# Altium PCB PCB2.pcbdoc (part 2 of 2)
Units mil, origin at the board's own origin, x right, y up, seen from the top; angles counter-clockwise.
Board outline 7114.17 x 3886.41 mil, 4 copper layers (Top Layer, Inner1, Inner2, Bottom Layer); 197 components, 125 nets, 754 pads, 711 vias.
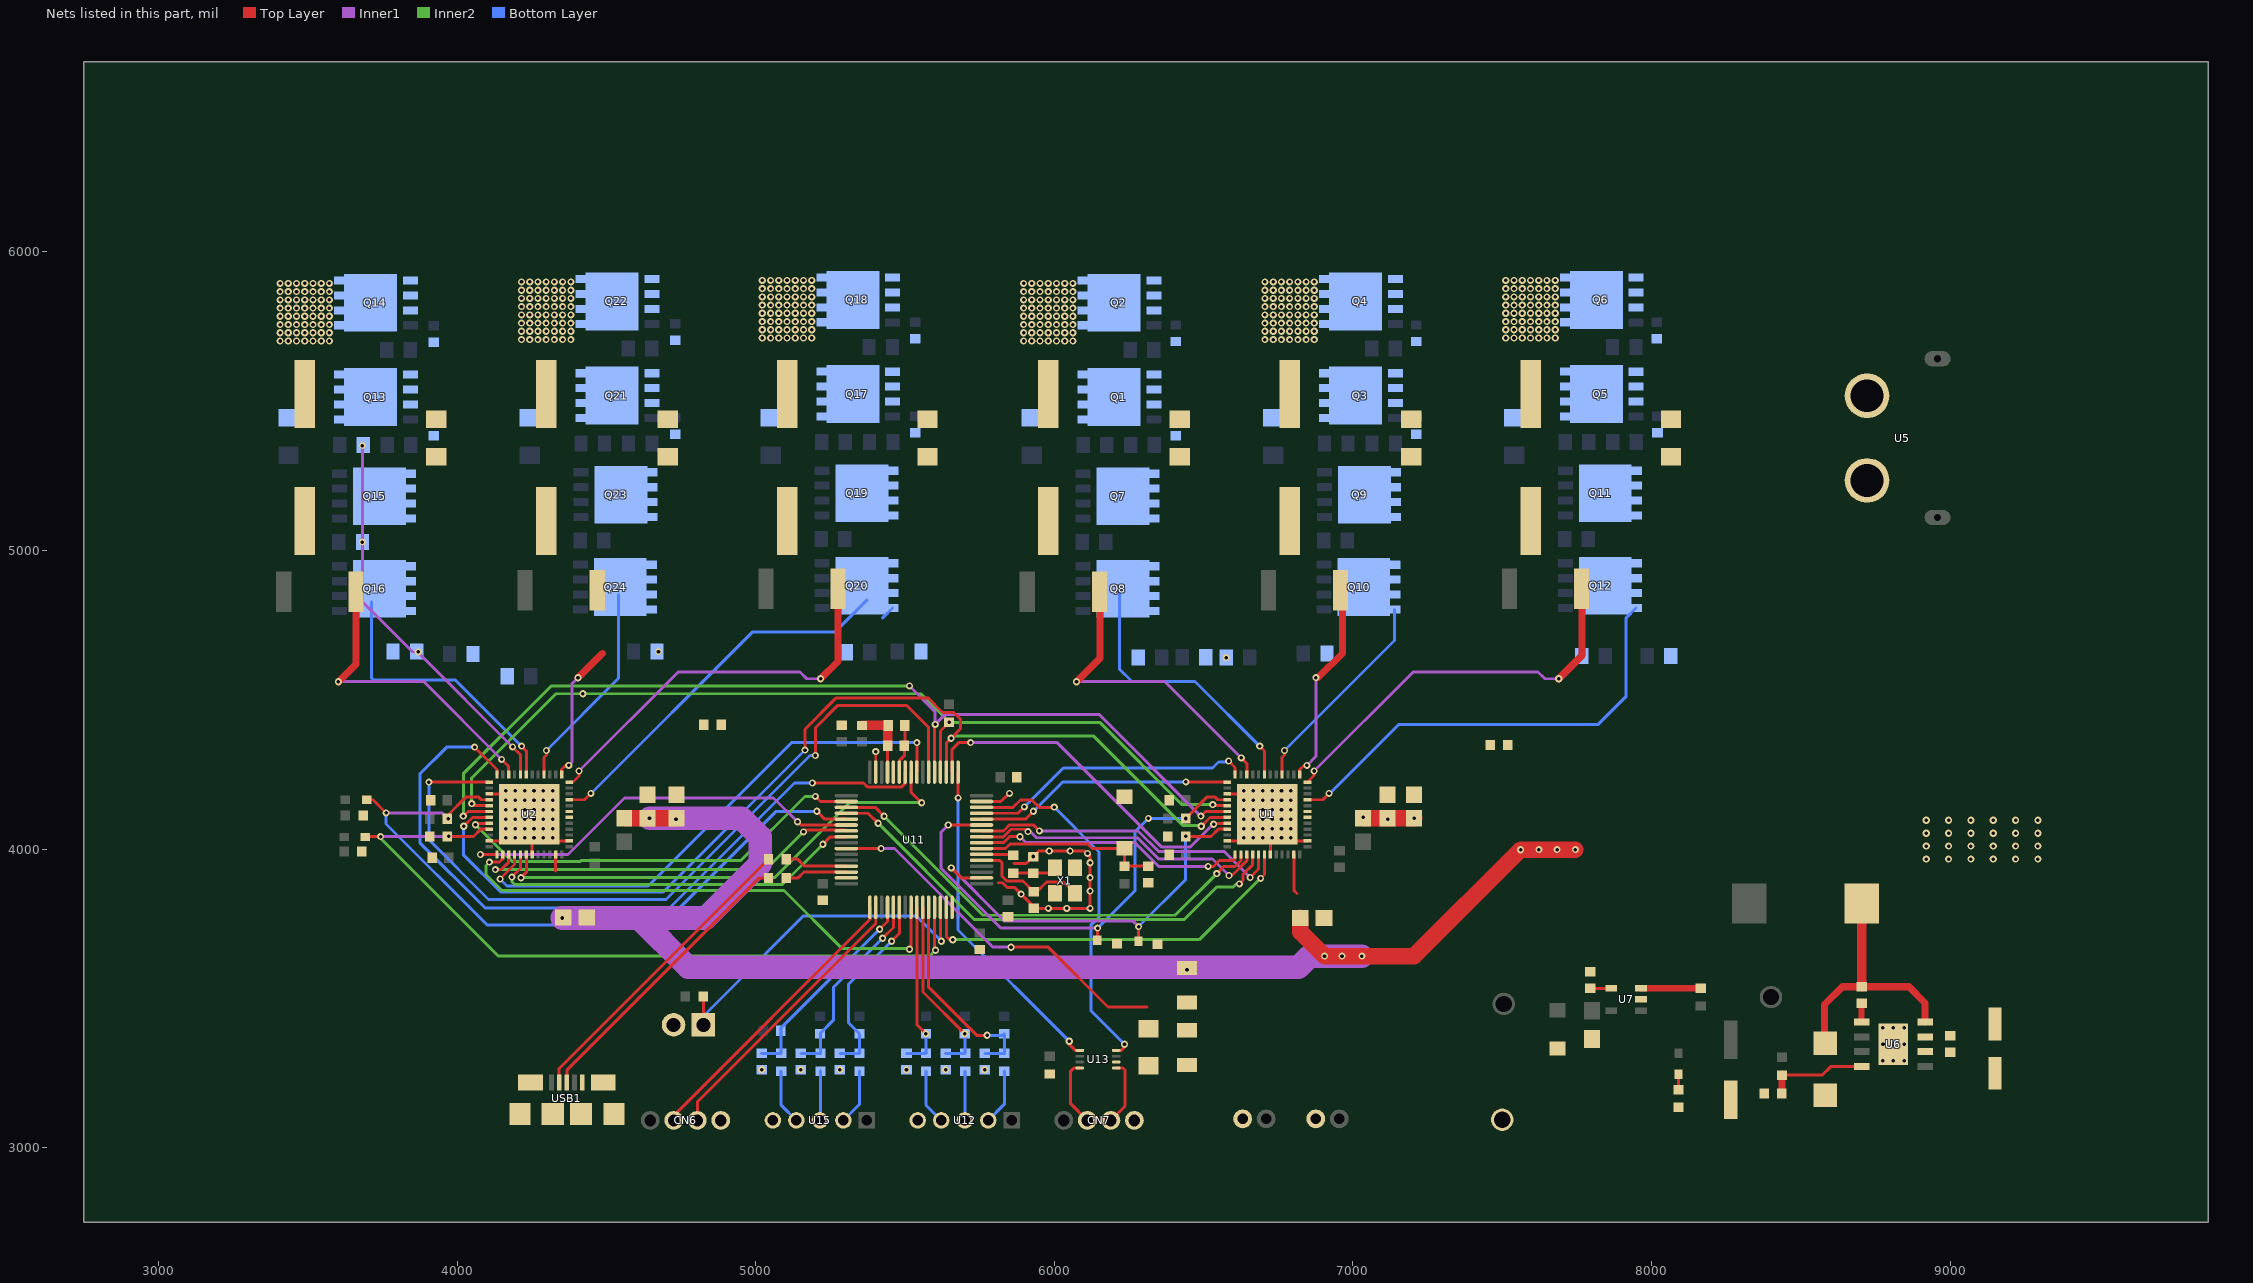
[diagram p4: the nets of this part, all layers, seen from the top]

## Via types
v1: diameter 24.02, hole 12.01, Top Layer to Bottom Layer, 707 vias
v2: diameter 236.22, hole 165.35, Top Layer to Bottom Layer, 4 vias

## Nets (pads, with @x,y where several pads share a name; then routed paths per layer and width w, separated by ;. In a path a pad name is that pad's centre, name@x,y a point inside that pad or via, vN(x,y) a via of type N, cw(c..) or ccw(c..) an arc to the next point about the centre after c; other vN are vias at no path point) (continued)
$1I3034\GL_C: R25.2 R43.2 R44.1 U2.20 | length 1331.4
  Top Layer w10: v1(4185.95,4342.16) 4212.2,4315.91 U2.20@4212.21,4250.15
  Inner1 w10: v1(3682.92,5351.41) v1(3682.92,5028.07) 3682.92,4828.7 3851.29,4660.34 v1(3869.92,4660.34) 3869.92,4658.19 v1(4185.95,4342.16)
$1N551: R75.1 R78.2 U6.4 | length 340.3
  Top Layer w10: R75.1@8436.66,3242.76 8571.35,3242.76 8600,3271.41 U6.4@8703.7,3271.41
  Top Layer w23.62: R78.2@8436.66,3181.41 R75.1@8436.66,3242.76
$1N561: C63.2 U6.1 | length 62.4
  Top Layer w19.68: U6.1@8703.7,3421.41 C63.2@8703.7,3483.85
$1N2428: C68.2 U7.4 | length 69.9
  Top Layer w10: C68.2@7795.03,3533.82 U7.4@7864.94,3533.82
$1N2597: R73.1 U7.3 | length 199.9
  Top Layer w21.65: U7.3@7965.06,3533.82 R73.1@8165,3533.82
$1N72792: C77.1 U11.5 X1.1 | length 412.8
  Top Layer w10: U11.5@5756.37,3962.51 5816.79,3962.51 5825.53,3953.77 5825.53,3907.92 5840.71,3892.74 5895.3,3892.74 C77.1@5930.76,3857.29 5941.45,3857.29 5974.12,3889.96 6030.68,3889.96 X1.1@6069.22,3851.42
$1N72945: R93.2 U11.6 | length 108.9
  Top Layer w10: U11.6@5756.37,3982.2 5861.79,3982.2 5862.27,3981.72 R93.2@5862.27,3978.92
$1N72949: C78.1 R93.1 X1.3 | length 147.7
  Top Layer w10: R93.1@5862.27,3919.6 C78.1@5928.95,3919.6 5983.86,3919.6 X1.3@6002.29,3938.04
$1N77944: R95.1 U11.46 | length 209.5
  Top Layer w10: R95.1@5102.19,3903.71 5142.3,3903.71 5161.73,3923.14 U11.46@5303.63,3923.14
$1N77945: R96.1 U11.45 | length 211
  Top Layer w10: R96.1@5102.19,3966.01 5140.4,3966.01 5163.58,3942.83 U11.45@5303.63,3942.83
$1N87601: LED5.1 R74.2 | length 51.6
  Top Layer w10: R74.2@8090,3194.38 LED5.1@8090,3245.98
$1N97516: R103.2 U12.4 | length 186.4
  Bottom Layer w10: R103.2@5570.53,3256.75 5570.53,3142.14 U12.4@5621.26,3091.41
$1N97530: R104.2 U12.3 | length 166
  Bottom Layer w10: U12.3@5700,3091.41 5701.58,3092.99 R104.2@5701.58,3256.75
$1N97534: R105.2 U12.2 | length 187.7
  Bottom Layer w10: U12.2@5778.74,3091.41 5832.63,3145.3 R105.2@5832.63,3256.75
$1N98528: R109.2 U15.4 | length 186.4
  Bottom Layer w10: R109.2@5085.53,3256.75 5085.53,3142.14 U15.4@5136.26,3091.41
$1N98530: R110.2 U15.3 | length 166
  Bottom Layer w10: U15.3@5215,3091.41 5216.58,3092.99 R110.2@5216.58,3256.75
$1N98532: R111.2 U15.2 | length 187.7
  Bottom Layer w10: U15.2@5293.74,3091.41 5347.63,3145.3 R111.2@5347.63,3256.75
AGND: C12.1 C13.1 C14.1 C15.1 C64.2 C65.2 C66.1 C67.2 C68.1 C69.1 C70.1 C71.1 C72.1 C73.1 C74.1 C75.1 C76.1 C77.2 C78.2 C80.1 C81.1 C82.1 C83.1 C84.1 C85.1 C86.1 CN3.1 CN4.2 CN5.2 CN6.1 CN7.1 D2.2 D3.2 H1.2 R19.1 R20.1 R21.1 R22.1 R24.1 R25.1 R26.1 R27.1 R28.1 R29.1 R30.1 R32.1 R33.1 R34.1 R35.1 R36.1 R37.1 R50.1 R74.1 R76.1 R77.1 R78.1 R87.1 R97.1 SW1.2 U1.2 U1.27 U1.35 U1.43 U1.49 U2.2 U2.27 U2.35 U2.43 U2.49 U6.6 U6.9 U7.2 U11.15 U11.27 U11.31 U11.47 U11.63 U12.5 U13.2 U15.5 USB1.5 USB1.6 X1.2 X1.4 | length 1610.1
  Top Layer w10: U2.35@4107.59,4027.42 U2.49@4153.15,4027.42 ; U2.27@4107.59,4184.9 4153.15,4184.9 v1(4162.99,4194.74) ; U2.49@4153.15,4022.5 U2.49@4162.99,4032.34 ; U2.43@4251.58,3981.85 4251.57,4031.35 v1(4257.48,4037.26) ; v1(4320.47,4037.26) 4330.31,4027.42 U2.2@4375.89,4027.42 ; U11.31@5402.05,4257.78 v1(5402.05,4326.41) ; U11.27@5480.79,4257.78 5480.79,4295.45 5497.56,4312.22 C75.1@5497.56,4346.41 5499.25,4348.1 C74.1@5499.25,4413.97 ; U11.15@5756.37,4159.36 5820.43,4159.36 5835.48,4174.4 5837.99,4174.4 v1(5850,4186.41) ; 5813.68,3887.25 5826.38,3887.25 5842.93,3870.7 5867.27,3870.7 v1(5888.9,3849.07) 5930.76,3807.21 C77.2@5930.76,3802.17 5931.51,3801.41 v1(5980.14,3801.41) v1(6041.48,3801.41) v1(6120,3801.41) v1(6120,3859.48) v1(6120,3904.39) v1(6120,3954.35) 6120,3976.41 6102.93,3993.48 v1(6052.86,3993.48) v1(5983.3,3993.48) 5947.71,3993.48 C78.2@5928.95,3974.72 ; 5865,3951.41 5905.91,3951.41 v1(5929.65,3975.15) ; U1.35@6579.37,4027.42 6624.94,4027.42 v1(6634.78,4037.26) ; U1.27@6579.37,4184.9 6624.94,4184.9 v1(6634.78,4194.74) ; U1.43@6723.36,3981.85 6723.36,4031.35 v1(6729.27,4037.26) ; v1(6792.26,4037.26) 6802.1,4027.42 U1.2@6847.67,4027.42
  other v1: 5020,3260.95 5151.05,3260.95 5282.1,3260.95 5505,3260.95 5636.05,3260.95 5767.1,3260.95 8775,3291.41 8810,3291.41 8845.83,3291.41 8775.1,3346.42 8810,3346.41 8845.83,3346.41 8775,3401.41 8810,3401.41 8845.83,3401.41 6111.06,3985.35 4162.99,4037.26 4194.49,4037.26 4225.98,4037.26 4288.97,4037.26 6666.27,4037.26 6697.77,4037.26 6760.76,4037.26 4162.99,4068.75 4194.49,4068.75 4225.98,4068.75 4257.48,4068.75 4288.97,4068.75 4320.47,4068.75 6634.78,4068.75 6666.27,4068.75 6697.77,4068.75 6729.27,4068.75 6760.76,4068.75 6792.26,4068.75 4162.99,4100.25 4194.49,4100.25 4225.98,4100.25 4257.48,4100.25 4288.97,4100.25 4320.47,4100.25 6634.78,4100.25 6666.27,4100.25 6697.77,4100.25 6729.27,4100.25 6760.76,4100.25 6792.26,4100.25 4162.99,4131.74 4194.49,4131.74 4225.98,4131.74 4257.48,4131.74 4288.97,4131.74 4320.47,4131.74 6634.78,4131.74 6666.27,4131.74 6697.77,4131.74 6729.27,4131.74 6760.76,4131.74 6792.26,4131.74 4162.99,4163.24 4194.49,4163.24 4225.98,4163.24 4257.48,4163.24 4288.97,4163.24 4320.47,4163.24 6634.78,4163.24 6666.27,4163.24 6697.77,4163.24 6729.27,4163.24 6760.76,4163.24 6792.26,4163.24 4194.49,4194.74 4225.98,4194.74 4257.48,4194.74 4288.97,4194.74 4320.47,4194.74 6666.27,4194.74 6697.77,4194.74 6729.27,4194.74 6760.76,4194.74 6792.26,4194.74 6575.63,4641.41 4674.43,4661.41
B1: CN7.3 U13.8 | length 222.7
  Top Layer w10: U13.8@6085.32,3266.88 6065.47,3266.88 6055,3256.41 6055,3147.04 CN7.3@6110.63,3091.41
B2: CN7.2 U13.1 | length 220.8
  Top Layer w10: CN7.2@6189.37,3091.41 6237.07,3139.11 6237.07,3259.81 6230,3266.88 U13.1@6207.36,3266.88
D+: R95.2 USB1.3 | length 983.3
  Top Layer w10: USB1.3@4367.66,3218.01 4367.66,3259.07 5012.3,3903.71 R95.2@5042.87,3903.71
D-: R96.2 USB1.2 | length 1038.3
  Top Layer w10: USB1.2@4342.07,3218.01 4342.07,3265.2 R96.2@5042.87,3966.01
M1_A: C30.1 C31.1 Q5.1 Q5.2 Q5.3 Q6.1 Q6.2 Q6.3 Q11.5 Q11.6 Q11.7 Q11.8 Q12.5 Q12.6 Q12.7 Q12.8 U1.9 | length 1520.2
  Top Layer w10: U1.9@6847.67,4165.21 6898.8,4165.21 v1(6920,4186.41)
  Bottom Layer w10: v1(6920,4186.41) 6922.48,4186.41 7152.48,4416.41 7820,4416.41 7915,4511.41 7915,4774.28 Q12.8@7947.93,4807.21
M1_B: C26.1 C27.1 Q3.1 Q3.2 Q3.3 Q4.1 Q4.2 Q4.3 Q9.5 Q9.6 Q9.7 Q9.8 Q10.5 Q10.6 Q10.7 Q10.8 U1.16 | length 708.3
  Top Layer w10: U1.16@6762.73,4250.15 6762.73,4307.14 6770.86,4315.27 v1(6770.86,4330.27)
  Bottom Layer w10: v1(6770.86,4330.27) 7139.15,4698.56 Q10.8@7139.15,4802.54
M1_C: C28.1 C29.1 Q1.1 Q1.2 Q1.3 Q2.1 Q2.2 Q2.3 Q7.5 Q7.6 Q7.7 Q7.8 Q8.5 Q8.6 Q8.7 Q8.8 U1.19 | length 951.9
  Top Layer w10: v1(6687.75,4344.67) 6703.68,4328.74 U1.19@6703.68,4250.15
  Bottom Layer w10: Q8.8@6230.17,4872.21 6217.93,4859.97 6217.93,4603.48 6260,4561.41 6471,4561.41 v1(6687.75,4344.67)
M2_A: C43.1 C44.1 Q17.1 Q17.2 Q17.3 Q18.1 Q18.2 Q18.3 Q19.5 Q19.6 Q19.7 Q19.8 Q20.5 Q20.6 Q20.7 Q20.8 U2.9 | length 1321.4
  Top Layer w10: U2.9@4375.89,4165.21 4427.01,4165.21 v1(4448.21,4186.41)
  Bottom Layer w10: v1(4448.21,4186.41) 4988.21,4726.41 5265,4726.41 Q20.8@5373.39,4834.8 ; 5425.18,4774.28 Q20.8@5458.11,4807.21
M2_B: C39.1 C40.1 Q21.1 Q21.2 Q21.3 Q22.1 Q22.2 Q22.3 Q23.5 Q23.6 Q23.7 Q23.8 Q24.5 Q24.6 Q24.7 Q24.8 U2.16 | length 704.9
  Top Layer w10: U2.16@4290.95,4250.15 4290.94,4307.14 4299.07,4315.27 v1(4299.07,4330.27)
  Bottom Layer w10: v1(4299.07,4330.27) 4540,4571.2 Q24.8@4540,4851.85
M2_C: C41.1 C42.1 Q13.1 Q13.2 Q13.3 Q14.1 Q14.2 Q14.3 Q15.5 Q15.6 Q15.7 Q15.8 Q16.5 Q16.6 Q16.7 Q16.8 U2.19 | length 952.2
  Top Layer w10: v1(4215.96,4344.67) 4231.89,4328.74 U2.19@4231.9,4250.15
  Bottom Layer w10: Q16.8@3712.93,4826.75 3712.93,4573.48 3720,4566.41 3994.22,4566.41 v1(4215.96,4344.67)
MISO: R94.1 U1.29 U2.29 U11.20 | length 3131.5
  Top Layer w10: v1(4048.85,4152.21) 4055.54,4145.53 U2.29@4109.37,4145.53 ; U11.20@5618.58,4257.78 5618.58,4395.65 v1(5648.09,4425.15) ; v1(6530.86,4148.83) 6534.16,4145.53 U1.29@6579.37,4145.53
  Inner2 w10: v1(4048.85,4152.21) 4048.85,4237.65 4331.36,4520.17 v1(4421.24,4520.17) 5553.07,4520.17 5623.84,4449.4 5624.52,4449.4 5637.99,4435.93 5637.99,4435.25 v1(5648.09,4425.15) 5648.84,4424.4 6152.01,4424.4 6427.58,4148.83 v1(6530.86,4148.83)
MOSI: U1.30 U2.30 U11.21 | length 3318.1
  Top Layer w10: v1(4020.86,4110.27) 4036.42,4125.84 U2.30@4109.37,4125.84 ; U11.21@5598.9,4257.78 5598.9,4415.31 v1(5601.26,4417.67) ; v1(6490.86,4110.27) 6506.42,4125.84 U1.30@6579.37,4125.84
  Inner1 w10: v1(5515,4546.41) 5601.26,4460.15 v1(5601.26,4417.67) 5635,4451.41 6149.71,4451.41 v1(6490.86,4110.27)
  Inner2 w10: v1(4020.86,4110.27) 4020.86,4252.27 4315,4546.41 v1(5515,4546.41)
NRST: C80.2 R98.1 SW1.1 U11.7 | length 631.3
  Top Layer w10: U11.7@5756.37,4001.88 5836.81,4001.88 5851.4,4016.47 6112.45,4016.47 6127.05,4001.88 6234.19,4001.88 SW1.1@6235,4002.69 R98.1@6235,3942.82 6314.06,3942.82 C80.2@6315,3941.88
PA0: U1.25 U11.12 | length 874.9
  Top Layer w10: U11.12@5756.37,4100.31 5903.9,4100.31 v1(5930,4126.41) ; v1(6440.52,4224.89) 6441.14,4224.27 U1.25@6579.37,4224.27
  Bottom Layer w10: v1(5930,4126.41) 6028.48,4224.89 v1(6440.52,4224.89)
PA1: U1.24 U11.13 | length 953.5
  Top Layer w10: U11.13@5756.37,4119.99 5878.58,4119.99 v1(5900,4141.41) ; v1(6583.81,4294.88) 6605.25,4273.45 U1.24@6605.25,4250.15
  Bottom Layer w10: v1(5900,4141.41) 6030,4271.41 6530,4271.41 6550,4291.41 6580.34,4291.41 v1(6583.81,4294.88)
PA4: U1.32 U11.18 | length 1185.3
  Top Layer w10: U11.18@5657.95,4257.78 5657.95,4334.36 5680,4356.41 v1(5719.57,4356.41) ; v1(6533.29,4083.16) 6536.59,4086.47 U1.32@6579.37,4086.47
  Inner1 w10: v1(5719.57,4356.41) 6010,4356.41 6360,4006.41 6454.51,4006.41 6531.27,4083.16 v1(6533.29,4083.16)
PA8: C76.2 R85.1 R87.2 U11.42 | length 1226.1
  Top Layer w10: U11.42@5303.63,4001.88 v1(5420,4001.88) ; v1(5855,3671.41) 5980,3671.41 6180,3471.41 6310,3471.41
  Inner1 w10: v1(5420,4001.88) 5464.53,4001.88 5795,3671.41 v1(5855,3671.41)
PA13: CN6.2 U11.50 | length 961.2
  Top Layer w10: CN6.2@4804.37,3091.41 4804.37,3153.3 5402.05,3750.98 U11.50@5402.05,3805.04
PA14: CN6.3 U11.49 | length 985.7
  Top Layer w10: CN6.3@4725.63,3091.41 4725.63,3107.04 5382.36,3763.77 U11.49@5382.36,3805.04
PB0: U2.40 U11.24 | length 1805.2
  Top Layer w10: v1(4144.08,3899.85) 4192.52,3948.29 U2.40@4192.53,3981.85 ; U11.24@5539.84,4257.78 5540,4257.94 v1(5540,4356.41)
  Bottom Layer w10: v1(4144.08,3899.85) 4167.52,3876.41 4640,3876.41 5120,4356.41 v1(5540,4356.41)
PB1: U2.42 U11.25 | length 1647.4
  Top Layer w10: v1(4214.06,3904.24) 4231.89,3922.06 U2.42@4231.9,3981.85 ; U11.25@5520.16,4257.78 5520.16,4190.72 v1(5555.46,4155.42)
  Inner2 w10: v1(4214.06,3904.24) 5062.83,3904.24 5314.01,4155.42 v1(5555.46,4155.42)
PB2: U2.24 U11.26 | length 2511.6
  Top Layer w10: v1(4058.55,4341.41) 4133.47,4266.49 U2.24@4133.47,4250.15 ; v1(5190,4221.41) 5361.38,4221.41 5375.36,4207.43 5487.79,4207.43 5500.47,4220.11 U11.26@5500.47,4257.78
  Bottom Layer w10: v1(4058.55,4341.41) 3965,4341.41 3875,4251.41 3875,4021.41 4094.02,3802.39 4710.98,3802.39 5130,4221.41 v1(5190,4221.41)
PB3: U2.38 U11.56 | length 1775.3
  Top Layer w10: v1(4108.21,3956.41) 4142.16,3956.41 4153.15,3967.4 U2.38@4153.16,3981.85 ; v1(5515,3664.4) 5520.16,3669.56 U11.56@5520.16,3805.04
  Inner2 w10: v1(4108.21,3956.41) 4096.53,3944.72 4096.53,3914.89 4150,3861.41 5095,3861.41 5290,3666.41 5512.99,3666.41 v1(5515,3664.4)
PB4: C81.2 R92.1 R103.1 U11.57 | length 567.1
  Top Layer w10: U11.57@5539.84,3805.04 5539.84,3411.57 v1(5570,3381.41)
  Bottom Layer w10: C81.2@5505,3316.07 R103.1@5570.53,3316.07 5570.53,3381.2 R92.1@5570.26,3381.46
PB5: C82.2 R91.1 R104.1 U11.58 | length 613.4
  Top Layer w10: U11.58@5559.53,3805.04 5560,3804.57 5560,3521.41 v1(5700,3381.41)
  Bottom Layer w10: C82.2@5636.05,3316.07 R104.1@5701.58,3316.07 5701.58,3379.88 R91.1@5700,3381.46
PB6: C83.2 R90.1 R105.1 U11.59 | length 720.9
  Top Layer w10: U11.59@5579.21,3805.04 5579.21,3537.2 5740,3376.41 v1(5775,3376.41)
  Bottom Layer w10: C83.2@5767.1,3316.07 R105.1@5832.63,3316.07 R90.1@5832.63,3381.46 5827.58,3376.41 v1(5775,3376.41)
PB7: LED4.2 R50.2 U2.33 U11.60 | length 2609.5
  Top Layer w10: LED4.2@3692.88,4040.21 3694.26,4041.59 v1(3743.77,4041.59) ; R50.2@3969.84,4042.3 4054.94,4042.3 4079.42,4066.79 U2.33@4109.37,4066.79 ; U11.60@5598.9,3805.04 5598.9,3664.71 v1(5602.2,3661.41)
  Inner1 w10: v1(3743.77,4041.59) 3970.77,4041.59 v1(3971.48,4042.3)
  Inner2 w10: v1(3743.77,4041.59) 3743.77,4036.59 4138.96,3641.41 5582.2,3641.41 v1(5602.2,3661.41)
PB8: H1.1 R99.1 U11.61 | length 1181.3
  Top Layer w10: R99.1@4823.98,3506.41 4825,3505.39 H1.1@4825,3411.41 ; U11.61@5618.58,3805.04 5618.58,3694.72 v1(5621.89,3691.41)
  Bottom Layer w10: H1.1@4825,3441.41 5160,3776.41 5536.89,3776.41 v1(5621.89,3691.41)
PB9: U1.42 U11.62 | length 1325.1
  Top Layer w10: U11.62@5638.27,3805.04 5638.27,3707.55 5649.41,3696.41 v1(5660,3696.41) ; v1(6690.85,3901.89) 6703.68,3914.72 U1.42@6703.68,3981.85
  Inner2 w10: v1(5660,3696.41) 6485.37,3696.41 v1(6690.85,3901.89)
PB12: U2.32 U11.34 | length 1438.5
  Top Layer w10: v1(4061.53,4081.41) 4066.59,4086.47 U2.32@4107.59,4086.47 ; v1(5200,4176.41) 5217.05,4159.36 U11.34@5303.63,4159.36
  Inner2 w10: v1(4061.53,4081.41) 4184.52,3958.42 4412.74,3958.42 4415.73,3961.41 4950,3961.41 5165,4176.41 v1(5200,4176.41)
PB13: U1.38 U11.35 | length 1567.2
  Top Layer w10: U11.35@5303.63,4139.68 5400,4139.68 v1(5430,4109.68) ; v1(6543.79,3917.71) 6567.48,3941.41 6605,3941.41 6624.94,3961.35 U1.38@6624.94,3981.85
  Inner2 w10: v1(5430,4109.68) 5761.26,3778.42 6404.49,3778.42 v1(6543.79,3917.71)
PB14: U1.40 U11.36 | length 1630.6
  Top Layer w10: U11.36@5303.63,4119.99 5376.42,4119.99 v1(5410,4086.41) ; v1(6620,3883.42) 6632.26,3895.68 6632.26,3915.68 6664.31,3947.73 U1.40@6664.31,3981.85
  Inner2 w10: v1(5410,4086.41) 5732.99,3763.42 6434.4,3763.42 6544.4,3873.42 6599.52,3873.42 6609.52,3883.42 v1(6620,3883.42)
PB15: LED3.2 R49.1 U2.28 U11.37 | length 2367
  Top Layer w10: LED3.2@3696.9,4165.21 3717.98,4165.21 v1(3762.08,4121.11) ; R49.1@3969.84,4102.48 3969.84,4114.38 4030.67,4175.21 4071.2,4175.21 4081.2,4165.21 U2.28@4109.37,4165.21 ; v1(5205,4126.41) 5231.1,4100.31 U11.37@5303.63,4100.31
  Inner1 w10: v1(3762.08,4121.11) 3950.3,4121.11 v1(3970,4101.41)
  Bottom Layer w10: v1(3762.08,4121.11) 3762.08,4084.33 4100.2,3746.21 4688.4,3746.21 5068.6,4126.41 v1(5205,4126.41)
PC0: U1.37 U11.8 | length 923.8
  Top Layer w10: U11.8@5756.37,4021.57 5830.16,4021.57 5850,4041.41 v1(5885,4041.41) ; v1(6515,3941.85) 6532.92,3941.85 6552.48,3961.41 6600,3961.41 6605.25,3966.66 U1.37@6605.25,3981.85
  Inner1 w10: v1(5885,4041.41) 5905,4021.41 6270,4021.41 6349.56,3941.85 v1(6515,3941.85)
PC1: U1.39 U11.9 | length 1004.1
  Top Layer w10: U11.9@5756.37,4041.25 5830.02,4041.25 5855.18,4066.41 5903.84,4066.41 v1(5911.83,4058.42) ; v1(6585,3911.41) 6594.82,3911.41 6644.62,3961.21 U1.39@6644.62,3981.85
  Inner1 w10: v1(5911.83,4058.42) 5920.01,4058.42 5940.48,4037.95 6278.46,4037.95 6350,3966.41 6530,3966.41 v1(6585,3911.41)
PC2: U1.41 U11.10 | length 1069.6
  Top Layer w10: U11.10@5756.37,4060.94 5829.89,4060.94 5850.36,4081.41 5929.53,4081.41 v1(5950,4060.94) ; v1(6655.85,3904.93) 6683.99,3933.07 U1.41@6683.99,3981.85
  Inner1 w10: v1(5950,4060.94) 6280.47,4060.94 6349.02,3992.39 6568.39,3992.39 v1(6655.85,3904.93)
PC3: LED1.2 R16.1 U1.28 U11.11 | length 1652.5
  Top Layer w10: v1(5645,4080.62) U11.11@5756.37,4080.62 ; LED1.2@6143.6,3694.04 6145.09,3695.53 v1(6145.09,3735.43) ; v1(6439.84,4102.48) 6512.56,4175.21 6536.99,4175.21 6546.99,4165.21 U1.28@6579.37,4165.21
  Inner1 w10: v1(5645,4080.62) 5620,4055.62 5620,3936.49 5821.06,3735.43 v1(6145.09,3735.43)
  Bottom Layer w10: v1(6145.09,3735.43) 6270,3860.34 6270,4057.63 v1(6315,4102.63) 6439.69,4102.63 v1(6439.84,4102.48)
PC4: U2.25 U11.22 | length 2655.6
  Top Layer w10: v1(3905.52,4224.27) U2.25@4107.59,4224.27 ; v1(5200,4313.42) 5200,4406.41 5275,4481.41 5505,4481.41 5579.21,4407.2 U11.22@5579.21,4257.78
  Bottom Layer w10: v1(3905.52,4224.27) 3905.52,4030.89 4105,3831.41 4700,3831.41 5182.01,4313.42 v1(5200,4313.42)
PC6: U2.37 U11.38 | length 1396.8
  Top Layer w10: v1(4078.21,3981.85) U2.37@4133.47,3981.85 ; v1(5140,4091.41) 5150.79,4080.62 U11.38@5303.63,4080.62
  Inner1 w10: v1(4078.21,3981.85) 4371.13,3981.85 4560.7,4171.41 5060,4171.41 v1(5140,4091.41)
PC7: U2.39 U11.39 | length 1312
  Top Layer w10: v1(4128.21,3931.41) 4148.21,3931.41 4172.83,3956.03 U2.39@4172.84,3981.85 ; v1(5160,4057.63) 5166.1,4063.73 5300.84,4063.73 U11.39@5303.63,4060.94
  Inner2 w10: v1(4128.21,3931.41) 5033.78,3931.41 v1(5160,4057.63)
PC8: U2.41 U11.40 | length 1293.1
  Top Layer w10: v1(4183.47,3906.16) 4212.2,3934.89 U2.41@4212.21,3981.85 ; v1(5225,4016.41) 5249.84,4041.25 U11.40@5303.63,4041.25
  Inner2 w10: v1(4183.47,3906.16) 4183.47,3891.25 4193.47,3881.25 5089.83,3881.25 v1(5225,4016.41)
PC10: C84.2 R108.1 R109.1 U11.52 | length 702.1
  Top Layer w10: v1(5415,3731.41) 5441.42,3757.83 U11.52@5441.42,3805.04
  Bottom Layer w10: C84.2@5020,3316.07 R109.1@5085.53,3316.07 5085.53,3381.2 5085.26,3381.46 5085.26,3401.67 v1(5415,3731.41)
PC11: C85.2 R107.1 R110.1 U11.53 | length 657.1
  Top Layer w10: v1(5425,3701.41) 5461.1,3737.51 U11.53@5461.1,3805.04
  Bottom Layer w10: C85.2@5151.05,3316.07 R110.1@5216.58,3316.07 5216.58,3379.88 R107.1@5215,3381.46 5260,3426.46 5260,3536.41 v1(5425,3701.41)
PC12: C86.2 R106.1 R111.1 U11.54 | length 640.8
  Top Layer w10: v1(5455,3691.41) 5480.79,3717.2 U11.54@5480.79,3805.04
  Bottom Layer w10: C86.2@5282.1,3316.07 R111.1@5347.63,3316.07 R106.1@5347.63,3381.46 5310,3419.09 5310,3546.41 v1(5455,3691.41)
PC13: LED2.2 R24.2 U1.33 U11.2 | length 1390.1
  Top Layer w10: v1(5654.65,3937.15) 5688.33,3903.46 U11.2@5756.37,3903.46 ; LED2.2@6282.12,3691.88 v1(6282.12,3740.43) ; v1(6439.84,4042.3) 6524.94,4042.3 6549.42,4066.79 U1.33@6579.37,4066.79
  Inner1 w10: v1(5654.65,3937.15) 5833.38,3758.42 6264.12,3758.42 v1(6282.12,3740.43)
  Bottom Layer w10: v1(6282.12,3740.43) 6439.84,3898.15 v1(6439.84,4042.3)
PGND: C1.1 C2.2 C3.1 C4.2 C5.1 C6.2 C10.2 C11.2 C18.2 C21.2 C22.2 C24.2 C25.2 C33.1 C34.1 C35.2 C37.1 C38.2 R13.1 R14.1 R15.1 R17.1 R18.1 R23.1 R76.2 R77.2 U1.12 U1.13 U1.22 U2.12 U2.13 U2.22 U5.4 | length 5935.5
  Top Layer w10: v1(4149.07,4300.27) 4172.84,4276.5 U2.22@4172.84,4250.15 ; U2.13@4350.01,4250.15 4350,4266.2 4364.07,4280.27 v1(4374.07,4280.27) ; U2.12@4375.89,4224.27 4387.85,4224.27 4408.21,4244.62 v1(4408.21,4261.41) ; v1(6625.86,4305.27) 6644.62,4286.51 U1.22@6644.62,4250.15 ; U1.13@6821.79,4250.15 6821.79,4266.2 6835.86,4280.27 v1(6845.86,4280.27) ; U1.12@6847.67,4224.27 6870,4246.6 v1(6870,4261.41)
  Top Layer w23.62: v1(3602.56,4560.44) 3660.9,4618.78 R17.1@3660.9,4861.41 ; v1(4404.9,4573.57) 4486.27,4654.94 ; v1(5217.56,4570.44) 5275.9,4628.78 R18.1@5275.9,4871.41 ; v1(6074.35,4560.44) 6152.94,4639.03 6152.94,4859.19 R13.1@6150.72,4861.41 ; v1(6876.1,4574.07) 6883.63,4574.07 6965,4655.44 6965,4860.4 R14.1@6959.12,4866.28 ; v1(7689.35,4570.44) 7767.94,4649.03 7767.94,4869.19 R15.1@7765.72,4871.41
  Inner1 w10: v1(3602.56,4560.44) 3888.9,4560.44 v1(4149.07,4300.27) ; v1(4374.07,4280.27) 4385,4291.2 4385,4553.67 v1(4404.9,4573.57) ; v1(4408.21,4261.41) 4740.23,4593.43 5148.34,4593.43 5171.34,4570.44 v1(5217.56,4570.44) ; v1(6074.35,4560.44) 6370.68,4560.44 v1(6625.86,4305.27) ; v1(6845.86,4280.27) 6876.1,4310.51 v1(6876.1,4574.07) ; v1(6870,4261.41) 7202.02,4593.43 7620.13,4593.43 7643.12,4570.44 v1(7689.35,4570.44)
PH: C63.1 D2.1 L3.2 U6.8 | length 858.2
  Top Layer w23.62: D2.1@8580,3347.73 8580,3478.85 8579.68,3479.17 8639.48,3538.97 C63.1@8703.7,3538.97 8862.44,3538.97 8916.3,3485.12 U6.8@8916.3,3421.41
  Top Layer w31.5: C63.1@8703.7,3538.97 L3.2@8703.7,3818.21
SCK: U1.31 U2.31 U11.19 | length 3514
  Top Layer w10: v1(4022.1,4076.51) 4051.74,4106.16 U2.31@4109.37,4106.16 ; v1(5165,4331.41) 5165,4401.23 5270.18,4506.41 5577.13,4506.41 5625.97,4457.57 5663.49,4457.57 5685.84,4435.22 5685.84,4402.68 v1(5654.57,4371.41) 5638.27,4355.11 U11.19@5638.27,4257.78 ; v1(6492.1,4076.51) 6521.74,4106.16 U1.31@6579.37,4106.16
  Inner2 w10: v1(5654.57,4371.41) 5662.56,4379.4 6130.4,4379.4 6430.31,4079.49 6489.12,4079.49 v1(6492.1,4076.51)
  Bottom Layer w10: v1(4022.1,4076.51) 4022.1,3979.31 4145,3856.41 4690,3856.41 v1(5165,4331.41)
UART_RX: U11.17 U13.5 | length 1109.4
  Top Layer w10: v1(5677.64,4171.41) U11.17@5677.64,4257.78 ; v1(6050,3356.41) 6050,3346.41 6070.47,3325.94 U13.5@6085.32,3325.94
  Bottom Layer w10: v1(5677.64,4171.41) 5677.64,3728.77 v1(6050,3356.41)
UART_TX: U11.14 U13.4 | length 1221.1
  Top Layer w10: U11.14@5756.37,4139.68 5861.76,4139.68 5886.48,4164.4 5924.52,4164.4 5949.25,4139.68 5999.06,4139.68 v1(6000,4140.62) ; U13.4@6207.36,3325.94 6224.53,3325.94 6235,3336.41 v1(6235,3346.41)
  Bottom Layer w10: v1(6000,4140.62) 6150,3990.62 6150,3772.86 6122.09,3744.95 6122.09,3459.32 v1(6235,3346.41)
VDDA: C74.2 C75.2 L4.2 U11.28 U11.29 | length 245
  Top Layer w10: U11.29@5441.42,4257.78 5441.42,4345.39 C75.2@5442.44,4346.41
  Top Layer w31.73: L4.2@5356.35,4413.94 5444.09,4413.94 5442.44,4412.29 C75.2@5442.44,4346.41
VM: C1.2 C2.1 C3.2 C4.1 C5.2 C6.1 C7.2 C8.2 C9.2 C10.1 C11.1 C17.2 C18.1 C20.2 C21.1 C22.1 C23.2 C24.1 C25.1 C32.2 C33.2 C34.2 C35.1 C36.2 C37.2 C38.1 C66.2 C67.1 Q1.5 Q1.6 Q1.7 Q1.8 Q2.5 Q2.6 Q2.7 Q2.8 Q3.5 Q3.6 Q3.7 Q3.8 Q4.5 Q4.6 Q4.7 Q4.8 Q5.5 Q5.6 Q5.7 Q5.8 Q6.5 Q6.6 Q6.7 Q6.8 Q13.5 Q13.6 Q13.7 Q13.8 Q14.5 Q14.6 Q14.7 Q14.8 Q17.5 Q17.6 Q17.7 Q17.8 Q18.5 Q18.6 Q18.7 Q18.8 Q21.5 Q21.6 Q21.7 Q21.8 Q22.5 Q22.6 Q22.7 Q22.8 R85.2 U1.6 U1.7 U1.47 U2.6 U2.7 U2.47 U5.3 U6.7 | length 5409.5
  Top Layer w10: 4330,3926.41 4330,3981.54 U2.47@4330.32,3981.85 ; U1.47@6802.1,3981.85 6802.1,3861.77 6812.46,3851.41
  Top Layer w55.51: C17.2@4562.58,4103.59 v1(4644.47,4103.59) C38.1@4733.21,4103.59 ; C24.1@6824.34,3769.2 6824.34,3722.07 v1(6905,3641.41) v1(6963.36,3641.41) v1(7030.22,3641.41) 7205,3641.41 v1(7561.55,3997.96) 7561.78,3998.19 v1(7622.7,3998.19) v1(7683.85,3998.19) v1(7745,3998.19) ; C20.2@7034.37,4103.59 C21.1@7116.26,4103.59 v1(7205,4103.59)
  Inner1 w78.74: v1(4352.55,3769.2) 4608.98,3769.2 ; v1(4644.47,4103.59) 4952.14,4103.59 5015,4040.73 5015,3951.41 4832.79,3769.2 4608.98,3769.2 ; v1(7030.22,3641.41) v1(6963.36,3641.41) v1(6905,3641.41) 6855,3641.41 6817.64,3604.05 4774.14,3604.05 4608.98,3769.2
  other v1: 6444.27,3596.09 8920,3966.49 8994.8,3966.49 9069.61,3966.49 9144.41,3966.49 9219.21,3966.49 9294.02,3966.49 8920,4009.8 8994.8,4009.8 9069.61,4009.8 9144.41,4009.8 9219.21,4009.8 9294.02,4009.8 8920,4053.1 8994.8,4053.1 9069.61,4053.1 9144.41,4053.1 9219.21,4053.1 9294.02,4053.1 8920,4096.41 8994.8,4096.41 9069.61,4096.41 9144.41,4096.41 9219.21,4096.41 9294.02,4096.41 4733.21,4100.54 7116.26,4100.54 7034.37,4106.64 3407.18,5701.49 3434.74,5701.49 3462.3,5701.49 3489.86,5701.49 3517.42,5701.49 3544.98,5701.49 3572.54,5701.49 5897.01,5701.49 5924.57,5701.49 5952.13,5701.49 5979.69,5701.49 6007.24,5701.49 6034.8,5701.49 6062.36,5701.49 4215.59,5706.36 4243.14,5706.36 4270.7,5706.36 4298.26,5706.36 4325.82,5706.36 4353.38,5706.36 4380.94,5706.36 6705.41,5706.36 6732.97,5706.36 6760.53,5706.36 6788.09,5706.36 6815.65,5706.36 6843.2,5706.36 6870.76,5706.36 5022.18,5711.49 5049.74,5711.49 5077.3,5711.49 5104.86,5711.49 5132.42,5711.49 5159.98,5711.49 5187.54,5711.49 7512.01,5711.49 7539.57,5711.49 7567.13,5711.49 7594.69,5711.49 7622.24,5711.49 7649.8,5711.49 7677.36,5711.49 3407.18,5729.05 3434.74,5729.05 3462.3,5729.05 3489.86,5729.05 3517.42,5729.05 3544.98,5729.05 3572.54,5729.05 5897.01,5729.05 5924.57,5729.05 5952.13,5729.05 5979.69,5729.05 6007.24,5729.05 6034.8,5729.05 6062.36,5729.05 4215.59,5733.92 4243.14,5733.92 4270.7,5733.92 4298.26,5733.92 4325.82,5733.92 4353.38,5733.92 4380.94,5733.92 6705.41,5733.92 6732.97,5733.92 6760.53,5733.92 6788.09,5733.92 6815.65,5733.92 6843.2,5733.92 6870.76,5733.92 5022.18,5739.05 5049.74,5739.05 5077.3,5739.05 5104.86,5739.05 5132.42,5739.05 5159.98,5739.05 5187.54,5739.05 7512.01,5739.05 7539.57,5739.05 7567.13,5739.05 7594.69,5739.05 7622.24,5739.05 7649.8,5739.05 7677.36,5739.05 3407.18,5756.61 3434.74,5756.61 3462.3,5756.61 3489.86,5756.61 3517.42,5756.61 3544.98,5756.61 3572.54,5756.61 5897.01,5756.61 5924.57,5756.61 5952.13,5756.61 5979.69,5756.61 6007.24,5756.61 6034.8,5756.61 6062.36,5756.61 4215.59,5761.48 4243.14,5761.48 4270.7,5761.48 4298.26,5761.48 4325.82,5761.48 4353.38,5761.48 4380.94,5761.48 6705.41,5761.48 6732.97,5761.48 6760.53,5761.48 6788.09,5761.48 6815.65,5761.48 6843.2,5761.48 6870.76,5761.48 5022.18,5766.61 5049.74,5766.61 5077.3,5766.61 5104.86,5766.61 5132.42,5766.61 5159.98,5766.61 5187.54,5766.61 7512.01,5766.61 7539.57,5766.61 7567.13,5766.61 7594.69,5766.61 7622.24,5766.61 7649.8,5766.61 7677.36,5766.61 3407.18,5784.17 3434.74,5784.17 3462.3,5784.17 3489.86,5784.17 3517.42,5784.17 3544.98,5784.17 3572.54,5784.17 5897.01,5784.17 5924.57,5784.17 5952.13,5784.17 5979.69,5784.17 6007.24,5784.17 6034.8,5784.17 6062.36,5784.17 4215.59,5789.04 4243.14,5789.04 4270.7,5789.04 4298.26,5789.04 4325.82,5789.04 4353.38,5789.04 4380.94,5789.04 6705.41,5789.04 6732.97,5789.04 6760.53,5789.04 6788.09,5789.04 6815.65,5789.04 6843.2,5789.04 6870.76,5789.04 5022.18,5794.17 5049.74,5794.17 5077.3,5794.17 5104.86,5794.17 5132.42,5794.17 5159.98,5794.17 5187.54,5794.17 7512.01,5794.17 7539.57,5794.17 7567.13,5794.17 7594.69,5794.17 7622.24,5794.17 7649.8,5794.17 7677.36,5794.17 3407.18,5811.73 3434.74,5811.73 3462.3,5811.73 3489.86,5811.73 3517.42,5811.73 3544.98,5811.73 3572.54,5811.73 5897.01,5811.73 5924.57,5811.73 5952.13,5811.73 5979.69,5811.73 6007.24,5811.73 6034.8,5811.73 6062.36,5811.73 4215.59,5816.59 4243.14,5816.59 4270.7,5816.59 4298.26,5816.59 4325.82,5816.59 4353.38,5816.59 4380.94,5816.59 6705.41,5816.59 6732.97,5816.59 6760.53,5816.59 6788.09,5816.59 6815.65,5816.59 6843.2,5816.59 6870.76,5816.59 5022.18,5821.73 5049.74,5821.73 5077.3,5821.73 5104.86,5821.73 5132.42,5821.73 5159.98,5821.73 5187.54,5821.73 7512.01,5821.73 7539.57,5821.73 7567.13,5821.73 7594.69,5821.73 7622.24,5821.73 7649.8,5821.73 7677.36,5821.73 3407.18,5839.28 3434.74,5839.28 3462.3,5839.28 3489.86,5839.28 3517.42,5839.28 3544.98,5839.28 3572.54,5839.28 5897.01,5839.28 5924.57,5839.28 5952.13,5839.28 5979.69,5839.28 6007.24,5839.28 6034.8,5839.28 6062.36,5839.28 4215.59,5844.15 4243.14,5844.15 4270.7,5844.15 4298.26,5844.15 4325.82,5844.15 4353.38,5844.15 4380.94,5844.15 6705.41,5844.15 6732.97,5844.15 6760.53,5844.15 6788.09,5844.15 6815.65,5844.15 6843.2,5844.15 6870.76,5844.15 5022.18,5849.28 5049.74,5849.28 5077.3,5849.28 5104.86,5849.28 5132.42,5849.28 5159.98,5849.28 5187.54,5849.28 7512.01,5849.28 7539.57,5849.28 7567.13,5849.28 7594.69,5849.28 7622.24,5849.28 7649.8,5849.28 7677.36,5849.28 3407.18,5866.84 3434.74,5866.84 3462.3,5866.84 3489.86,5866.84 3517.42,5866.84 3544.98,5866.84 3572.54,5866.84 5897.01,5866.84 5924.57,5866.84 5952.13,5866.84 5979.69,5866.84 6007.24,5866.84 6034.8,5866.84 6062.36,5866.84 4215.59,5871.71 4243.14,5871.71 4270.7,5871.71 4298.26,5871.71 4325.82,5871.71 4353.38,5871.71 4380.94,5871.71 6705.41,5871.71 6732.97,5871.71 6760.53,5871.71 6788.09,5871.71 6815.65,5871.71 6843.2,5871.71 6870.76,5871.71 5022.18,5876.84 5049.74,5876.84 5077.3,5876.84 5104.86,5876.84 5132.42,5876.84 5159.98,5876.84 5187.54,5876.84 7512.01,5876.84 7539.57,5876.84 7567.13,5876.84 7594.69,5876.84 7622.24,5876.84 7649.8,5876.84 7677.36,5876.84 3407.18,5894.4 3434.74,5894.4 3462.3,5894.4 3489.86,5894.4 3517.42,5894.4 3544.98,5894.4 3572.54,5894.4 5897.01,5894.4 5924.57,5894.4 5952.13,5894.4 5979.69,5894.4 6007.24,5894.4 6034.8,5894.4 6062.36,5894.4 4215.59,5899.27 4243.14,5899.27 4270.7,5899.27 4298.26,5899.27 4325.82,5899.27 4353.38,5899.27 4380.94,5899.27 6705.41,5899.27 6732.97,5899.27 6760.53,5899.27 6788.09,5899.27 6815.65,5899.27 6843.2,5899.27 6870.76,5899.27 5022.18,5904.4 5049.74,5904.4 5077.3,5904.4 5104.86,5904.4 5132.42,5904.4 5159.98,5904.4 5187.54,5904.4 7512.01,5904.4 7539.57,5904.4 7567.13,5904.4 7594.69,5904.4 7622.24,5904.4 7649.8,5904.4 7677.36,5904.4
pads on no net: U1.1 U1.23 U1.34 U1.44 U1.45 U1.46 U1.48 U2.1 U2.23 U2.34 U2.44 U2.45 U2.46 U2.48 U5.1 U5.2 U6.2 U6.3 U6.5 U11.3 U11.4 U11.23 U11.30 U11.33 U11.41 U11.43 U11.44 U11.51 U11.55 USB1.1 USB1.4
copper on no net: | length 151.1
  Top Layer w10: 6821.79,3981.85 6821.79,3949.62 6871.78,3899.63 6871.78,3851.41
  other v2: 3157.48,3158.1 9456.69,3158.1 3157.48,6228.97 9456.69,6228.97

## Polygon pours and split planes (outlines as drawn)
VM on Bottom Layer (solid, remove dead copper, pour order 42): 7481.31,5935.43 7903.75,5935.43 7903.75,5416.41 7481.31,5416.41
$1I2936\A_H on Top Layer (solid, remove dead copper, pour order 0): 7495,4971.41 7685,4971.41 7685,4711.41 7495,4711.41
5V on Inner2 (solid, remove dead copper): 3420,3576.41 8470,3576.41 8470,3021.41 3420,3021.41
VM on Inner1 (solid, remove dead copper): 7000,4131.41 9310,4131.41 9310,3916.41 7000,3916.41
$1I2936\A_H on Bottom Layer (solid, remove dead copper, pour order 44): 7485,5343.67 7736.6,5343.67 7736.6,4786.41 7485,4786.41
$1I2936\C_H on Top Layer (solid, remove dead copper, pour order 2): 5880,4961.41 6070,4961.41 6070,4701.41 5880,4701.41
AGND on Inner1 (solid, remove dead copper): 5878.51,4001.88 6128.56,4001.88 6128.56,3801.41 5878.51,3801.41
3.3V on Inner1 (solid, remove dead copper): 3414.79,4625.47 7727.27,4625.47 7727.27,3024.92 3414.79,3024.92
AGND on Inner2 (solid, remove dead copper): 3423.21,4701.41 8865,4701.41 8865,3021.41 3423.21,3021.41
$1I2936\B_H on Top Layer (solid, remove dead copper, pour order 4): 6690,4971.41 6880,4971.41 6880,4711.41 6690,4711.41
M1_A on Bottom Layer (solid, remove dead copper, pour order 46): 7756.6,6306.41 8229.04,6306.41 8229.04,4785.76 7756.6,4785.76
VM on Bottom Layer (solid, remove dead copper, pour order 48): 5866.31,5925.43 6288.75,5925.43 6288.75,5406.41 5866.31,5406.41
$1I2936\C_H on Bottom Layer (solid, remove dead copper, pour order 50): 5870,5348.67 6121.6,5348.67 6121.6,4776.41 5870,4776.41
$1I3034\A_H on Top Layer (solid, remove dead copper, pour order 10): 5008.21,4971.41 5213.21,4971.41 5213.21,4711.41 5008.21,4711.41
M1_C on Bottom Layer (solid, remove dead copper, pour order 52): 6141.6,6321.41 6614.04,6321.41 6614.04,4775.76 6141.6,4775.76
VM on Bottom Layer (solid, remove dead copper, pour order 54): 6674.71,5930.3 7097.15,5930.3 7097.15,5411.28 6674.71,5411.28
M1_B on Bottom Layer (solid, remove dead copper, pour order 56): 6950,6316.28 7422.44,6316.28 7422.44,4780.63 6950,4780.63
$1I2936\B_H on Bottom Layer (solid, remove dead copper, pour order 58): 6679.2,5347.54 6930.8,5347.54 6930.8,4770.28 6679.2,4770.28
VM on Top Layer (solid, remove dead copper, pour order 16): 3397.19,5936.41 9325,5936.41 9325,5409.11 3397.19,5409.11
AGND on Bottom Layer (solid, remove dead copper, pour order 60): 3415,4701.41 8865,4701.41 8865,3021.41 3415,3021.41
VM on Top Layer (solid, remove dead copper, pour order 18): 8890.71,5411.41 9320,5411.41 9320,3359.21 8890.71,3359.21
$1I3034\B_H on Top Layer (solid, remove dead copper, pour order 20): 4195,4971.41 4400,4971.41 4400,4701.41 4195,4701.41
VM on Bottom Layer (solid, remove dead copper, pour order 62): 4991.49,5935.43 5413.93,5935.43 5413.93,5416.41 4991.49,5416.41
$1I3034\A_H on Bottom Layer (solid, remove dead copper, pour order 64): 4995.18,5343.67 5246.77,5343.67 5246.77,4786.41 4995.18,4786.41
$1I3034\C_H on Top Layer (solid, remove dead copper, pour order 22): 3387.5,4966.41 3592.5,4966.41 3592.5,4706.41 3387.5,4706.41
PGND on Top Layer (solid, remove dead copper, pour order 24): 3385.25,5346.41 8850,5346.41 8850,4701.41 3385.25,4701.41
M2_A on Bottom Layer (solid, remove dead copper, pour order 66): 5266.77,6306.41 5739.21,6306.41 5739.21,4785.76 5266.77,4785.76
VM on Bottom Layer (solid, remove dead copper, pour order 68): 3376.49,5925.43 3798.93,5925.43 3798.93,5406.41 3376.49,5406.41
PGND on Top Layer (solid, remove dead copper, pour order 26): 4405,4711.41 4850,4711.41 4850,3721.41 4405,3721.41
$1I3034\C_H on Bottom Layer (solid, remove dead copper, pour order 70): 3380.18,5348.67 3631.77,5348.67 3631.77,4776.41 3380.18,4776.41
PGND on Top Layer (solid, remove dead copper, pour order 28): 6867.34,4713.75 7477.34,4713.75 7477.34,3743.75 6867.34,3743.75
5V on Top Layer (solid, remove dead copper, pour order 30): 8065,3886.41 8480,3886.41 8480,3286.41 8065,3286.41
M2_C on Bottom Layer (solid, remove dead copper, pour order 72): 3651.77,6311.41 4124.21,6311.41 4124.21,4775.76 3651.77,4775.76
3.3V on Top Layer (solid, remove dead copper, pour order 32): 7310,3576.41 7727.26,3576.41 7727.26,3384.92 7310,3384.92
VM on Bottom Layer (solid, remove dead copper, pour order 74): 4184.89,5930.3 4607.33,5930.3 4607.33,5411.28 4184.89,5411.28
AGND on Top Layer (solid, remove dead copper, pour order 34): 8860,3336.41 9315,3336.41 9315,3021.41 8860,3021.41
M2_B on Bottom Layer (solid, remove dead copper, pour order 76): 4460.18,6311.28 4932.62,6311.28 4932.62,4780.63 4460.18,4780.63
PA8 on Top Layer (solid, remove dead copper, pour order 36): 6479.27,3368.93 6279.27,3368.93 6279.27,3508.93 6479.27,3508.93
$1I3034\B_H on Bottom Layer (solid, remove dead copper, pour order 78): 4189.38,5342.54 4440.97,5342.54 4440.97,4770.28 4189.38,4770.28
VDDA on Top Layer (solid, remove dead copper, pour order 38): 5435,4301.41 5465.43,4301.41 5465.43,4215.71 5435,4215.71
AGND on Top Layer (solid, remove dead copper, pour order 40): 3414.79,4671.19 8865,4671.19 8865,3021.41 3414.79,3021.41
AGND on Inner2 (solid, remove dead copper): 5793.2,4013.11 5793.2,3944.13 5833.35,3903.98 5892.79,3903.98 5955.81,3840.96 6084.07,3840.96 6098.93,3826.09 6098.93,3975.8 6097.1,3977.64 5971.87,3977.64 5936.87,4012.64 5793.67,4012.64 5793.2,4013.11
VM on Top Layer (solid, remove dead copper, pour order 6): 6796.59,3968.75 6796.59,3743.02 6855,3743.02 6855,3801.41 6825,3831.41 6825,3911.41 6807.61,3928.8 6807.61,3968.75
VM on Top Layer (solid, remove dead copper, pour order 8): 6835.76,4131.35 7010,4131.35 7010,4076.41 6960,4076.41 6935,4101.41 6835.76,4101.41
VM on Top Layer (solid, remove dead copper, pour order 12): 4324.8,3968.75 4324.8,3743.02 4383.21,3743.02 4383.21,3801.41 4353.21,3831.41 4353.21,3911.41 4335.82,3928.8 4335.82,3968.75
VM on Top Layer (solid, remove dead copper, pour order 14): 4363.97,4131.35 4538.21,4131.35 4538.21,4076.41 4488.21,4076.41 4463.21,4101.41 4363.97,4101.41

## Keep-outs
Board Outline Layer:
  lines w10: 3000,3000.58 9614.17,3000.58 9614.17,6386.41 3000,6386.41 3000,3000.58

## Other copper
Bottom Layer:
  region net M2_B: 4654.32,4773.76 4644.32,4773.76 ccw(c4625.57,4773.76) 4636.82,4788.76 4661.82,4788.76 ccw(c4673.07,4773.76)

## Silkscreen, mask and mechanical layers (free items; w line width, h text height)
Top Silkscreen Layer:
  text "RESET" at 6179.02,4201.73 h39.37
  text "Fault" at 3495,4131.41 h39.37
  text "EN" at 3540,3996.41 h39.37
  text "Fault" at 6130,3551.41 h39.37
  text "EN" at 6280,3551.41 h39.37
  text "BOOT" at 5410,3536.41 h39.37
  text "SWCLK" at 4625,3211.41 h39.37
  text "SWDIO" at 4800,3211.41 h39.37
  text "TX" at 6154.69,3207.28 h39.37
  text "RX" at 6075,3206.41 h39.37
Bottom Solder Mask Layer:
  region: 3651.78,6311.41 4120,6311.41 4120,5957.08 3651.78,5957.08
  region: 4465.89,6303.58 4934.11,6303.58 4934.11,5949.25 4465.89,5949.25
  region: 5270.89,6303.58 5739.11,6303.58 5739.11,5949.25 5270.89,5949.25
  region: 6145.89,6318.58 6614.11,6318.58 6614.11,5964.25 6145.89,5964.25
  region: 6955.89,6313.58 7424.11,6313.58 7424.11,5959.25 6955.89,5959.25
  region: 7755.89,6308.58 8224.11,6308.58 8224.11,5954.25 7755.89,5954.25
